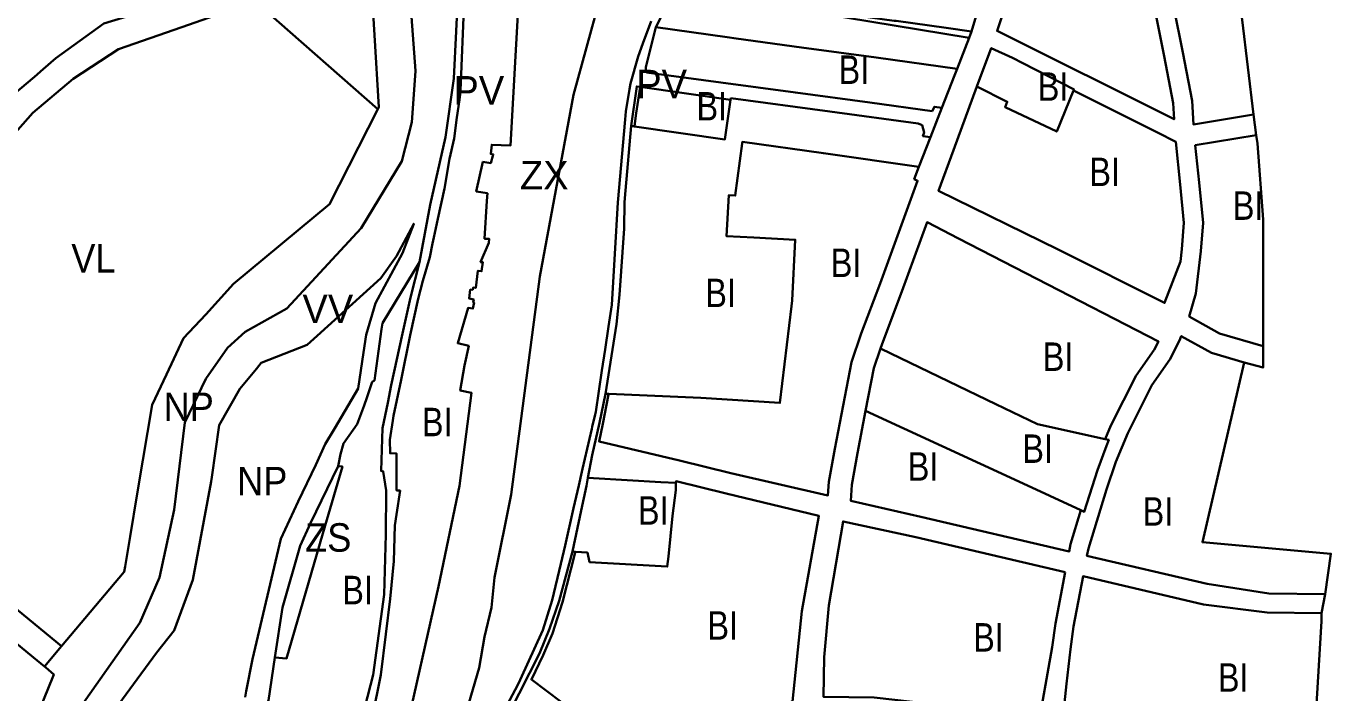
# Model space of a CAD drawing. Extents: x -650451 to -642268, y -1075216 to -1066610.
# Drawn here: x -646147 to -645459, y -1069937 to -1069586 of the extents above; entities that cross this region are included whole.
import ezdxf

# ---------------------------------------------------------------- set-up
doc = ezdxf.new("R2010")
doc.units = 0
doc.header["$LTSCALE"] = 6
doc.layers.add('1', color=7, linetype='Continuous', lineweight=35)
doc.layers.add('2', color=7, linetype='Continuous')
doc.layers.add('3', color=7, linetype='Continuous')

msp = doc.modelspace()

# ---------------------------------------------------------------- linework, layer by layer
at = {"layer": '1'}
for p, q in [((-645648.68, -1069589.06), (-645649.91, -1069592.39)), ((-645649.91, -1069592.39), (-645656.15, -1069608.71)), ((-645775.46, -1069625.13), (-645823.082, -1069618.279)), ((-645664.19, -1069629.24), (-645670.23, -1069644.67)), ((-645500.137, -1069632.833), (-645498.61, -1069643.729)), ((-645827.94, -1069638.8), (-645826.15, -1069639.045)), ((-645676.34, -1069660.28), (-645670.23, -1069644.67)), ((-645839.658, -1069779.835), (-645841.41, -1069779.76)), ((-646222.694, -1069834.722), (-646127.84, -1069912.695)), ((-645857.204, -1069862.954), (-645858.78, -1069862.84)), ((-645464.288, -1069895.362), (-645462.303, -1069885.376)), ((-646127.84, -1069912.695), (-646136.88, -1069923.39))]:
    msp.add_line(p, q, dxfattribs=at)
for points in [[(-645508.994, -1069447.955), (-645511.585, -1069450.466), (-645524.812, -1069463.425), (-645534.584, -1069477.365), (-645543.548, -1069494.404), (-645547.654, -1069514.049), (-645548.207, -1069534.609), (-645546.74, -1069552.954), (-645537.354, -1069600.095), (-645532.36, -1069625.648), (-645531.753, -1069637.96), (-645500.137, -1069632.833)], [(-645500.137, -1069632.833), (-645506, -1069583), (-645511, -1069544), (-645512, -1069499), (-645484.783, -1069488.256), (-645493, -1069471), (-645501, -1069458), (-645508.994, -1069447.955)], [(-645957.35, -1069496.35), (-645944.19, -1069571.66), (-645941.5, -1069609.76), (-645942.58, -1069624.73), (-645943.44, -1069636.76), (-645948.61, -1069657.43), (-645970.08, -1069692.61), (-646009.2, -1069734.98), (-646031.15, -1069747.2), (-646040.53, -1069755.58), (-646051.95, -1069771.98), (-646062.91, -1069794.85), (-646068.64, -1069840.94), (-646076.24, -1069876.52), (-646086.68, -1069900.4), (-646121.75, -1069950.24), (-646124.96, -1069959.99)], [(-645961.36, -1069630.05), (-645960.78, -1069628.91), (-645965.36, -1069552.99), (-645977.73, -1069509.11), (-646004.7, -1069517.16)], [(-646018.55, -1069514.14), (-646028.24, -1069555.37), (-646028.96, -1069558.45), (-646029.48, -1069558.67), (-646046.26, -1069565.81), (-646054.54, -1069569.34), (-646068.61, -1069573.63), (-646105.58, -1069584.91), (-646130.94, -1069603.1), (-646137.61, -1069608.96), (-646142.14, -1069612.9), (-646153.18, -1069622.24), (-646166.94, -1069635.16), (-646169.42, -1069637.65), (-646176.16, -1069644.04), (-646195.87, -1069662.74), (-646205.34, -1069680.08), (-646207.96, -1069697.21), (-646203.82, -1069728.79), (-646200.67, -1069752.88)], [(-645939.36, -1069710.47), (-645933.68, -1069680.28), (-645925.69, -1069644.69), (-645921.18, -1069613.78), (-645918.82, -1069563.81)], [(-645887.067, -1069570.398), (-645891.363, -1069649.02), (-645901.32, -1069648.67), (-645901.85, -1069653.55), (-645900.51, -1069653.79), (-645901.83, -1069658.33), (-645905.98, -1069657.74), (-645909.48, -1069673.29), (-645903.58, -1069674.25), (-645903.91, -1069678.31), (-645905.06, -1069698.17), (-645902.71, -1069698.19), (-645902.74, -1069700.28), (-645907.14, -1069710.44), (-645906, -1069710.47), (-645906.6, -1069715.28), (-645908.59, -1069715.03), (-645909.72, -1069724.11), (-645911.16, -1069723.93), (-645911.28, -1069725.04), (-645912.61, -1069724.96), (-645913.16, -1069729.73), (-645910.73, -1069730.15), (-645911, -1069731.7), (-645910.62, -1069731.78), (-645911.19, -1069734.97), (-645913.78, -1069734.57), (-645919.21, -1069753.23), (-645913.36, -1069754.55), (-645915.56, -1069764.88), (-645917.9, -1069778.03), (-645911.909, -1069779.311), (-645918.332, -1069828.187), (-645929.263, -1069881.347), (-645947.741, -1069963.127)], [(-645643.16, -1069570.6), (-645644.56, -1069575.61), (-645648.68, -1069589.06)], [(-646027.49, -1069571.79), (-646033.46, -1069575.84), (-646064.48, -1069586.72), (-646097.88, -1069598.43), (-646121.76, -1069613.94), (-646142.99, -1069631.85), (-646168.19, -1069660.3), (-646181.86, -1069675.73), (-646188.9, -1069692.13), (-646190.58, -1069708.64), (-646187.15, -1069740.55), (-646186.2, -1069749.43), (-646187.53, -1069750.63), (-646186.24, -1069769.06), (-646186.66, -1069775.09), (-646187.9, -1069781.01), (-646188.76, -1069783.97), (-646187.68, -1069788.27), (-646188.83, -1069794.63), (-646222.694, -1069834.722)], [(-646027.49, -1069571.79), (-646020.4, -1069578.04), (-645961.36, -1069630.05)], [(-645964.26, -1069950.41), (-645959.68, -1069927.82), (-645957.04, -1069906.36), (-645954.82, -1069887.72), (-645952.79, -1069868), (-645952.27, -1069849.2), (-645951.37, -1069843.39), (-645949.58, -1069830.77), (-645951.42, -1069830.72), (-645951.38, -1069811.33), (-645954.79, -1069811.15), (-645954.96, -1069804.13), (-645953.4, -1069793.8), (-645953.05, -1069791.5), (-645948.99, -1069772.41), (-645944.19, -1069748.94), (-645940.1, -1069729.8), (-645937.55, -1069720.4), (-645933.83, -1069707.8), (-645932.41, -1069700.69), (-645931.77, -1069697.53), (-645929.67, -1069687.75), (-645926.22, -1069671.74), (-645923.49, -1069656.16), (-645921.13, -1069645.4), (-645919.6, -1069634.34), (-645918.23, -1069625.11), (-645917.74, -1069620.86), (-645917.68, -1069620.16), (-645915.79, -1069573.09)], [(-645916.63, -1069954.05), (-645907.94, -1069924.17), (-645905.05, -1069907.69), (-645901.48, -1069892.25), (-645899.79, -1069876.56), (-645890.981, -1069832.79), (-645875.912, -1069718.128), (-645858.275, -1069622.412), (-645844.534, -1069572.473)], [(-645649.91, -1069592.39), (-645727.71, -1069579.61), (-645803.33, -1069571.62), (-645808.18, -1069573.7), (-645814.82, -1069586.81)], [(-645741.14, -1069576.19), (-645689.41, -1069583.4), (-645688.37, -1069583.55), (-645661.92, -1069587.22), (-645648.68, -1069589.06)], [(-645901.65, -1069959.39), (-645887.58, -1069932.97), (-645886.36, -1069930.34), (-645874.3, -1069904.18), (-645869.52, -1069888.49), (-645864.82, -1069869.41), (-645862.61, -1069859.66), (-645858.16, -1069840.07), (-645855.44, -1069828.02), (-645853.79, -1069820.9), (-645853.43, -1069819.25), (-645848.62, -1069798.2), (-645848.4, -1069797.22), (-645846.88, -1069790.69), (-645846.55, -1069789.26), (-645843.3, -1069767.6), (-645841.63, -1069756.5), (-645839.82, -1069744.44), (-645838.11, -1069733.06), (-645836.53, -1069706.1), (-645834.96, -1069679.16), (-645831.04, -1069635.33), (-645830.66, -1069631.11), (-645828.73, -1069619.42), (-645828.21, -1069616.41), (-645824.15, -1069602.16), (-645821.66, -1069595.43), (-645817.3, -1069583.61)], [(-645814.82, -1069586.81), (-645820.17, -1069607.8), (-645820.2, -1069609.32), (-645819.7, -1069610.66), (-645780.55, -1069615.94), (-645741.38, -1069621.23), (-645702.1, -1069626.53), (-645669.38, -1069630.95), (-645668.15, -1069628.71), (-645664.19, -1069629.24)], [(-645814.82, -1069586.81), (-645777.26, -1069592.07), (-645772.58, -1069592.73), (-645738.13, -1069597.46), (-645698.83, -1069602.85), (-645656.15, -1069608.71)], [(-645645.715, -1069618.085), (-645638.203, -1069597.8), (-645626.95, -1069602.91), (-645621.56, -1069605.68), (-645594.58, -1069619.56), (-645594.818, -1069620.139)], [(-645656.15, -1069608.71), (-645657.52, -1069612.2), (-645664.19, -1069629.24)], [(-645823.082, -1069618.279), (-645824.95, -1069618.01), (-645827.94, -1069638.8)], [(-645823.082, -1069618.279), (-645823.13, -1069618.452), (-645825.295, -1069632.053), (-645826.133, -1069638.843), (-645826.15, -1069639.045)], [(-645594.818, -1069620.139), (-645550.62, -1069642.176), (-645541.064, -1069647.092), (-645538.744, -1069669.644), (-645536.707, -1069689.842), (-645537.8, -1069703.696), (-645538.579, -1069710.102), (-645546.93, -1069731.98), (-645602.91, -1069703.88), (-645665.961, -1069673.028), (-645658.119, -1069651.601), (-645645.715, -1069618.085)], [(-645645.715, -1069618.085), (-645629.78, -1069626.03), (-645630.93, -1069628.84), (-645603.7, -1069641.75), (-645594.818, -1069620.139)], [(-645826.15, -1069639.045), (-645826.151, -1069639.057), (-645778.45, -1069645.92), (-645775.46, -1069625.13)], [(-645670.23, -1069644.67), (-645674.19, -1069644.14), (-645673.62, -1069642.3), (-645674.67, -1069638.47), (-645676.72, -1069637.53), (-645723.18, -1069631.26), (-645775.33, -1069624.21), (-645775.46, -1069625.13)], [(-645961.36, -1069630.05), (-645986.71, -1069679.91), (-646037.33, -1069721.89), (-646051.95, -1069738.02), (-646063.59, -1069750.57), (-646072.6, -1069769.62), (-646080.14, -1069785.63), (-646085.07, -1069814.68), (-646088.02, -1069832.44), (-646091.72, -1069854.99), (-646094.33, -1069870.67), (-646094.82, -1069873.63), (-646127.84, -1069912.695)], [(-645827.94, -1069638.8), (-645830.77, -1069672.75), (-645831.35, -1069678.9), (-645831.62, -1069692.74), (-645834.01, -1069727.78), (-645835.59, -1069743.21), (-645841.41, -1069779.76)], [(-645495, -1069754.815), (-645518, -1069748), (-645533.953, -1069739.166), (-645530.534, -1069726.969), (-645527.824, -1069704.697), (-645526.643, -1069689.732), (-645528.772, -1069668.628), (-645530.797, -1069648.949), (-645498.61, -1069643.729)], [(-645498.61, -1069643.729), (-645498, -1069648), (-645495, -1069688), (-645495, -1069754.815)], [(-645676.34, -1069660.28), (-645726.57, -1069653.22), (-645769.264, -1069647.213), (-645769.36, -1069648), (-645773.02, -1069675.47), (-645776.45, -1069675.26), (-645777.62, -1069696.85), (-645763.24, -1069697.58), (-645741.43, -1069698.68), (-645743.01, -1069730.72), (-645743.36, -1069733.7), (-645749.48, -1069784.61), (-645791.2, -1069781.92), (-645839.658, -1069779.835)], [(-645839.658, -1069779.835), (-645839.721, -1069780.247), (-645842.728, -1069795.578), (-645844.737, -1069804.875), (-645802.431, -1069814.987), (-645775.326, -1069821.576), (-645724.25, -1069833.353), (-645723.777, -1069826.243), (-645720.632, -1069808.792), (-645711.852, -1069763.14), (-645706.663, -1069747.998), (-645696.794, -1069721.756), (-645676.984, -1069667.634), (-645678.73, -1069666.78), (-645676.34, -1069660.28)], [(-646031.24, -1069939.45), (-646030.62, -1069936.3), (-646027.3, -1069919.47), (-646012.37, -1069856.22), (-646003.18, -1069836.56), (-645993.96, -1069817.23), (-645989.01, -1069806.25), (-645983.89, -1069797.86), (-645971.7, -1069777.05), (-645968.78, -1069758.13), (-645967.35, -1069748.81), (-645962.48, -1069732.04), (-645948.22, -1069705.79), (-645942.41, -1069690.26), (-645951.52, -1069707.28), (-645959.63, -1069718.95), (-645993.22, -1069749.24), (-645998.57, -1069754.06), (-646022.72, -1069763.59), (-646025.11, -1069766.63), (-646034.02, -1069777.19), (-646044.94, -1069796.35), (-646048.71, -1069823.79), (-646049, -1069825.93), (-646058.71, -1069877.82), (-646068.5, -1069904.5), (-646077.78, -1069916.11), (-646104.04, -1069951.75)], [(-645578.134, -1069803.731), (-645575.153, -1069796.472), (-645561.956, -1069770.224), (-645552.437, -1069756.749), (-645550.184, -1069752.242), (-645614.28, -1069719.27), (-645655.45, -1069698.05), (-645671.999, -1069689.523), (-645685.351, -1069726.002), (-645695.176, -1069752.125), (-645696.517, -1069756.039)], [(-645939.36, -1069710.47), (-645958.9, -1069742.7), (-645959.35, -1069745.74), (-645963.06, -1069772.82), (-645964.34, -1069773.6), (-645967.15, -1069781.97), (-645968.57, -1069785.9), (-645972.16, -1069795.77), (-645979.38, -1069805.93), (-645980.87, -1069811.56), (-645982.12, -1069817.85)], [(-645968.18, -1069944.85), (-645963.78, -1069927.8), (-645957.97, -1069885.45), (-645957.1, -1069853.97), (-645956.81, -1069830.65), (-645958.46, -1069820.67), (-645959.56, -1069820.45), (-645958.82, -1069797.9), (-645956.06, -1069784.57), (-645954.27, -1069775.33), (-645948.32, -1069748.06), (-645944.06, -1069729.12), (-645939.36, -1069710.47)], [(-645462.303, -1069885.376), (-645492, -1069885), (-645524.43, -1069879.921), (-645587.785, -1069865.117), (-645587.052, -1069861.272), (-645577.497, -1069830.237), (-645572.56, -1069815.628), (-645566.341, -1069800.49), (-645553.635, -1069775.217), (-645544.108, -1069761.733), (-645539.126, -1069751.764), (-645538.096, -1069749.446), (-645522.277, -1069758.205), (-645504.976, -1069763.332)], [(-645704.355, -1069788.786), (-645700.028, -1069766.286), (-645696.517, -1069756.039)], [(-645696.517, -1069756.039), (-645660.57, -1069773.31), (-645635.79, -1069785.23), (-645613.84, -1069795.78), (-645578.134, -1069803.731)], [(-645495, -1069754.815), (-645495, -1069766), (-645504.976, -1069763.332)], [(-645462.303, -1069885.376), (-645459.312, -1069864.01), (-645527, -1069858), (-645504.976, -1069763.332)], [(-645841.41, -1069779.76), (-645844.57, -1069795.07), (-645848.35, -1069812.09), (-645850.63, -1069824.09)], [(-645704.355, -1069788.786), (-645708.633, -1069811.027), (-645711.644, -1069827.736), (-645712.203, -1069836.131), (-645675.369, -1069844.625), (-645597.216, -1069862.91), (-645596.458, -1069858.935), (-645590.964, -1069841.09)], [(-645590.964, -1069841.09), (-645623.75, -1069825.97), (-645704.355, -1069788.786)], [(-645578.134, -1069803.731), (-645576.34, -1069804.13), (-645577.52, -1069807.26), (-645582.31, -1069820.05), (-645589.23, -1069841.89), (-645590.964, -1069841.09)], [(-646015.46, -1069918.63), (-646011.51, -1069892.38), (-646002.25, -1069859.77), (-645996.72, -1069847.96), (-645982.12, -1069817.85)], [(-645982.12, -1069817.85), (-645979.96, -1069818.11), (-645989.11, -1069849.11), (-646009.34, -1069919.12), (-646015.46, -1069918.63)], [(-645858.78, -1069862.84), (-645854.18, -1069841.21), (-645851.44, -1069828.34), (-645850.63, -1069824.09)], [(-645804.28, -1069826.76), (-645812.18, -1069826.3), (-645847.62, -1069824.26), (-645850.63, -1069824.09)], [(-645857.204, -1069862.954), (-645857.289, -1069863.338), (-645863.95, -1069889.468), (-645869.262, -1069905.935), (-645874.219, -1069917.496), (-645880.431, -1069930.3), (-645833, -1069966), (-645806, -1069959), (-645768.424, -1069948.431), (-645742.967, -1069941.862), (-645738.039, -1069894.231), (-645729.006, -1069844.136), (-645777.852, -1069832.241), (-645804.185, -1069825.84), (-645804.28, -1069826.76)], [(-645804.28, -1069826.76), (-645804.38, -1069830.61), (-645806.07, -1069844.09), (-645808.28, -1069865.39), (-645808.84, -1069870.75), (-645849.79, -1069868.4), (-645850.92, -1069863.41), (-645857.204, -1069862.954)], [(-646231.73, -1069845.42), (-646203.48, -1069868.65), (-646142.68, -1069918.62), (-646136.88, -1069923.39)], [(-645858.78, -1069862.84), (-645865.78, -1069888.76), (-645870.89, -1069903.5), (-645876.15, -1069916.47), (-645892.09, -1069947.98), (-645895.66, -1069958.42), (-645894.25, -1069958.7)], [(-645464.288, -1069895.362), (-645492.842, -1069895), (-645526.451, -1069890.745), (-645589.84, -1069875.892), (-645594.866, -1069902.242), (-645596.463, -1069914.335), (-645598.491, -1069932.472), (-645601.753, -1069962.317), (-645547.4, -1069976.382), (-645490.814, -1069988.074), (-645469.701, -1069990.011)], [(-645464.288, -1069895.362), (-645464.206, -1069899.449), (-645469.701, -1069990.011)], [(-646035.42, -1069980.12), (-646029.65, -1069960.92), (-646018.88, -1069941.32), (-646015.46, -1069918.63)], [(-646136.88, -1069923.39), (-646136.23, -1069923.94), (-646131.96, -1069927.57), (-646135.28, -1069935.88), (-646136.46, -1069938.84), (-646152.59, -1069978.9), (-646160.09, -1069997.51)]]:
    msp.add_lwpolyline(points, dxfattribs=at)
for points in [[(-645555.072, -1069500.545), (-645608.04, -1069466.749), (-645612.028, -1069487.724), (-645619.662, -1069532.642), (-645623.814, -1069549.548), (-645629.102, -1069570.857), (-645635.153, -1069588.78), (-645541.922, -1069635.264), (-645542.336, -1069626.862), (-645547.188, -1069602.035), (-645556.685, -1069554.337), (-645558.241, -1069534.874), (-645557.65, -1069512.879)], [(-645599.271, -1069873.685), (-645677.849, -1069855.3), (-645716.277, -1069847.01), (-645723.668, -1069891.356), (-645726.131, -1069918.457), (-645726.542, -1069939.398), (-645699.889, -1069939.714), (-645670.325, -1069943.002), (-645625.979, -1069954.92), (-645614.072, -1069957.797), (-645606.07, -1069913.163), (-645604.424, -1069900.701)]]:
    msp.add_lwpolyline(points, close=True, dxfattribs=at)

# ---------------------------------------------------------------- texts
at = {"layer": '2'}
for s, width, p in [('BI', 0.85, (-645718.61, -1069616.699)), ('BI', 0.85, (-645613.688, -1069625.566)), ('VL', 0.95, (-646122.736, -1069715.973)), ('BI', 0.85, (-645788.805, -1069734.183)), ('NP', 0.95, (-646074.148, -1069794.146)), ('BI', 0.85, (-645938.061, -1069802.161)), ('BI', 0.85, (-645621.816, -1069816.199)), ('BI', 0.85, (-645824.272, -1069848.711)), ('ZS', 0.95, (-645999.58, -1069862.95)), ('BI', 0.85, (-645979.993, -1069890.643))]:
    msp.add_text(s, height=15, dxfattribs=dict(at, width=width)).set_placement(p)
for s, p in [('PV', (-645921.483, -1069627.552)), ('ZX', (-645886.44, -1069672.23)), ('VV', (-646000.991, -1069742.547))]:
    msp.add_text(s, height=15, dxfattribs=at).set_placement(p)
at = {"layer": '3'}
msp.add_text('PV', height=15, dxfattribs=at).set_placement((-645825.191, -1069624.25))
for s, width, p in [('BI', 0.85, (-645793.45, -1069635.932)), ('BI', 0.85, (-645586.525, -1069670.465)), ('BI', 0.85, (-645510.976, -1069688.242)), ('BI', 0.85, (-645722.71, -1069718.341)), ('BI', 0.85, (-645611.051, -1069767.781)), ('BI', 0.85, (-645682.157, -1069825.553)), ('NP', 0.95, (-646035.399, -1069833.278)), ('BI', 0.85, (-645558.464, -1069849.256)), ('BI', 0.85, (-645787.703, -1069909.252)), ('BI', 0.85, (-645647.715, -1069915.547)), ('BI', 0.85, (-645518.838, -1069936.656))]:
    msp.add_text(s, height=15, dxfattribs=dict(at, width=width)).set_placement(p)

doc.saveas('drawing.dxf')
